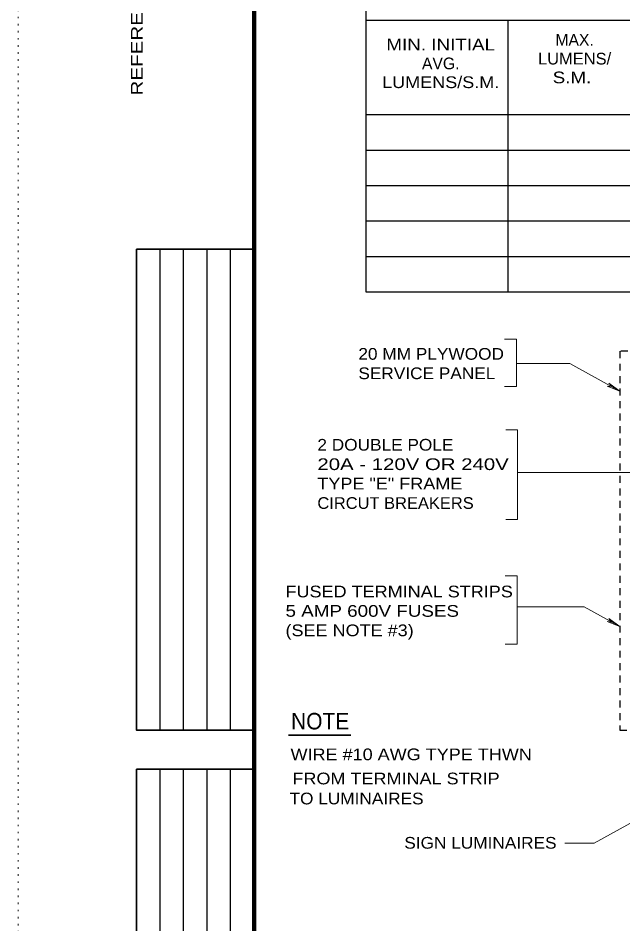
# Model space of a CAD drawing. Extents: x 312583 to 312854, y 144419 to 144597.
# Drawn here: x 312601.2 to 312640.4, y 144478 to 144536.8 of the extents above; entities that cross this region are included whole.
import ezdxf
from ezdxf.enums import TextEntityAlignment as Align

# ---------------------------------------------------------------- set-up
doc = ezdxf.new("R2010")
doc.units = 0
doc.header["$LTSCALE"] = 0.3
doc.linetypes.add('DOTTED', pattern=[1.5, 0.3, -1.2])
doc.linetypes.add('SHORT_DASHED', pattern=[2.7, 1.5, -1.2])
doc.layers.add('1', color=7, linetype='Continuous', lineweight=13)
doc.layers.add('63', color=7, linetype='DOTTED', lineweight=13)

msp = doc.modelspace()

# ---------------------------------------------------------------- linework, layer by layer
at = {"layer": '1', "lineweight": 158}
msp.add_line((312616.5, 144423.0846), (312616.5, 144585.0846), dxfattribs=at)
at = {"layer": '1', "lineweight": 25}
for p, q in [((312623.7553, 144540.3271), (312623.7553, 144519.0521)), ((312623.7553, 144536.6855), (312672.8219, 144536.6855)), ((312632.9553, 144536.6855), (312632.9553, 144519.0521)), ((312623.7553, 144530.5521), (312672.8219, 144530.5521)), ((312623.7553, 144528.2521), (312672.8219, 144528.2521)), ((312623.7553, 144525.9521), (312672.8219, 144525.9521)), ((312623.7553, 144523.6521), (312672.8219, 144523.6521)), ((312610.4087, 144490.5973), (312610.4087, 144521.8156)), ((312611.9315, 144490.5973), (312611.9315, 144521.8156)), ((312613.4543, 144490.5973), (312613.4543, 144521.8156)), ((312614.9772, 144490.5973), (312614.9772, 144521.8156)), ((312623.7553, 144521.3521), (312672.8219, 144521.3521)), ((312623.7553, 144519.0521), (312672.8219, 144519.0521)), ((312610.4087, 144456.841), (312610.4087, 144488.0592)), ((312611.9315, 144456.841), (312611.9315, 144488.0592)), ((312613.4543, 144456.841), (312613.4543, 144488.0592)), ((312614.9772, 144456.841), (312614.9772, 144488.0592))]:
    msp.add_line(p, q, dxfattribs=at)
at = {"layer": '1'}
for p, q in [((312633.5152, 144515.9802), (312632.7485, 144515.9802)), ((312633.5152, 144514.3997), (312636.9825, 144514.3997)), ((312640.2159, 144512.6145), (312636.9825, 144514.3997)), ((312633.5152, 144512.9135), (312632.7485, 144512.9135)), ((312639.4032, 144512.9365), (312639.6945, 144512.8982)), ((312640.2159, 144512.6145), (312639.4032, 144512.9365)), ((312639.5029, 144513.1282), (312639.6945, 144512.8982)), ((312640.2159, 144512.6145), (312639.5029, 144513.1282)), ((312633.5919, 144510.0998), (312632.8252, 144510.0998)), ((312633.5919, 144507.3238), (312641.4655, 144507.3238)), ((312633.5919, 144504.2732), (312632.8252, 144504.2732)), ((312633.5535, 144500.6238), (312632.7869, 144500.6238)), ((312633.5535, 144498.6039), (312637.9105, 144498.6039)), ((312640.2159, 144497.3348), (312637.9105, 144498.6039)), ((312639.4032, 144497.6568), (312639.6945, 144497.6185)), ((312640.2159, 144497.3348), (312639.4032, 144497.6568)), ((312639.5029, 144497.8408), (312639.6945, 144497.6185)), ((312640.2159, 144497.3348), (312639.5029, 144497.8408)), ((312633.5535, 144496.1772), (312632.7869, 144496.1772)), ((312642.9835, 144485.7122), (312638.5675, 144483.2742)), ((312636.6509, 144483.2742), (312638.5675, 144483.2742))]:
    msp.add_line(p, q, dxfattribs=at)
at = {"layer": '1', "linetype": 'SHORT_DASHED', "lineweight": 25}
msp.add_line((312640.2159, 144490.6035), (312668.2835, 144490.6035), dxfattribs=at)
at = {"layer": '1', "lineweight": 35}
msp.add_line((312618.724, 144490.2736), (312622.7668, 144490.2736), dxfattribs=at)
for points in [[(312616.5, 144490.5973), (312608.8858, 144490.5973), (312608.8858, 144521.8156), (312616.5, 144521.8156)], [(312616.5, 144456.841), (312608.8858, 144456.841), (312608.8858, 144488.0592), (312616.5, 144488.0592)]]:
    msp.add_lwpolyline(points, dxfattribs=at)
at = {"layer": '1'}
for points in [[(312633.5152, 144515.9802), (312633.5152, 144515.1368), (312633.5152, 144512.9135)], [(312633.5919, 144510.0998), (312633.5919, 144509.2565), (312633.5919, 144504.2732)], [(312633.5535, 144500.6238), (312633.5535, 144499.7805), (312633.5535, 144496.1772)]]:
    msp.add_lwpolyline(points, dxfattribs=at)
at = {"layer": '1', "linetype": 'SHORT_DASHED', "lineweight": 25}
msp.add_lwpolyline([(312668.2835, 144515.1982), (312668.2835, 144515.1982), (312640.2159, 144515.1982), (312640.2159, 144490.6035)], dxfattribs=at)
at = {"layer": '63'}
msp.add_line((312601.2, 144418.5846), (312601.2, 144596.7846), dxfattribs=at)

# ---------------------------------------------------------------- texts
at = {"layer": '1', "width": 1.3}
msp.add_text('REFERENCE                                                              ', height=0.7682, rotation=90, dxfattribs=at).set_placement((312609.2854, 144531.7949))
at = {"layer": '1'}
for s, p in [('MAX.', (312637.2888, 144535.0275)), ('AVG.', (312628.6053, 144533.4971))]:
    msp.add_text(s, height=0.76, dxfattribs=at).set_placement(p, align=Align.CENTER)
for s, height, width, p in [('MIN. INITIAL', 0.76, 1.2, (312628.6053, 144534.7171)), ('LUMENS/', 0.76, 1.05, (312637.2888, 144533.8075)), ('S.M. ', 0.76, 1.2, (312637.2888, 144532.5875)), ('LUMENS/S.M.', 0.76, 1.15, (312628.6053, 144532.2771)), ('NOTE', 1.07, 0.95, (312620.7885, 144490.6486))]:
    msp.add_text(s, height=height, dxfattribs=dict(at, width=width)).set_placement(p, align=Align.CENTER)
for s, width, p in [('20 MM PLYWOOD', 1.1, (312623.2648, 144514.6442)), ('SERVICE PANEL', 1.1, (312623.2648, 144513.3842)), ('2 DOUBLE POLE', 1.1, (312620.607, 144508.7432)), ('20A - 120V OR 240V', 1.3, (312620.607, 144507.4832)), ('TYPE "E" FRAME', 1.15, (312620.607, 144506.2232)), ('CIRCUT BREAKERS', 1.05, (312620.607, 144504.9632)), ('FUSED TERMINAL STRIPS', 1.15, (312618.5403, 144499.2192)), ('5 AMP 600V FUSES', 1.2, (312618.5403, 144497.9592)), ('(SEE NOTE #3)', 1.15, (312618.5403, 144496.6992)), ('WIRE #10 AWG TYPE THWN', 1.15, (312618.8662, 144488.6481)), ('FROM TERMINAL STRIP', 1.15, (312618.9883, 144487.0822)), ('TO LUMINAIRES', 1.1, (312618.7992, 144485.7832)), ('SIGN LUMINAIRES', 1.1, (312626.2434, 144482.9068))]:
    msp.add_text(s, height=0.76, dxfattribs=dict(at, width=width)).set_placement(p)

doc.saveas('drawing.dxf')
